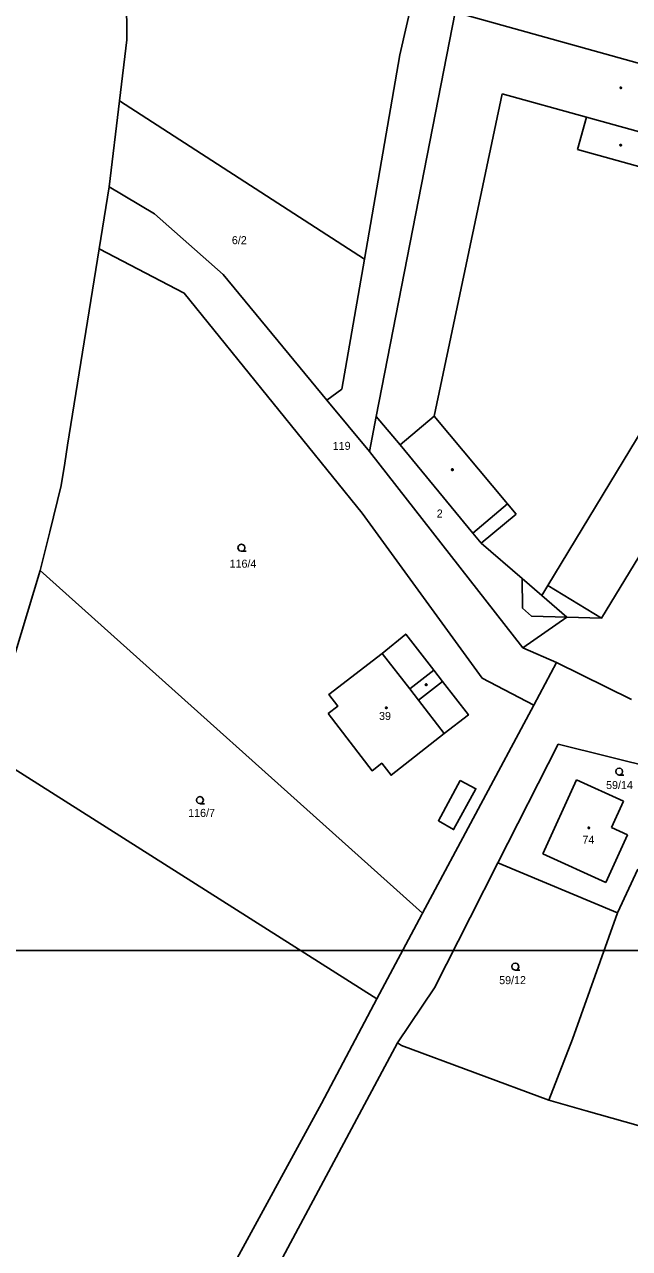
# Model space of a CAD drawing. Extents: x -752500 to -750336, y -1035826 to -1033500.
# Drawn here: x -751692 to -751563.4, y -1034563.3 to -1034303.4 of the extents above; entities that cross this region are included whole.
import ezdxf

# ---------------------------------------------------------------- set-up
doc = ezdxf.new("R2010")
doc.units = 0
for name, color, linetype in [('Default', 7, 'Continuous'), ('Hranice parcel', 7, 'Continuous'), ('ML1000', 7, 'Continuous'), ('Parcelní čísla', 7, 'Continuous'), ('Vnitřní kresba', 7, 'Continuous'), ('Věcná břemena k části', 7, 'Continuous'), ('Značky budov', 7, 'Continuous'), ('Značky kultur', 7, 'Continuous')]:
    doc.layers.add(name, color=color, linetype=linetype)

# ---------------------------------------------------------------- blocks, each defined once
blk = doc.blocks.new('304')
at = {"layer": 'Default'}
blk.add_lwpolyline([(0, 0), (-0.38, 0.1), (-0.65, 0.37), (-0.75, 0.74), (-0.65, 1.11), (-0.38, 1.38), (-0.01, 1.48), (0.36, 1.38), (0.63, 1.11), (0.73, 0.73), (0.63, 0.35), (0.36, 0.08), (-0.02, -0.02), (0.98, -0.02)], dxfattribs=at)
blk = doc.blocks.new('402')
at = {"layer": 'Default'}
blk.add_lwpolyline([(0.09, 0.15), (0.18, 0), (0.09, -0.15), (-0.09, -0.15), (-0.18, 0), (-0.09, 0.15), (0.09, 0.15)], dxfattribs=at)

msp = doc.modelspace()

# ---------------------------------------------------------------- linework, layer by layer
at = {"layer": 'Hranice parcel'}
for p, q in [((-751670.81, -1034226.35), (-751670.25, -1034306.59)), ((-751612.23, -1034309.8), (-751603.35, -1034270.82)), ((-751600.51, -1034300.74), (-751617.27, -1034386.59)), ((-751671.8, -1034319.6), (-751670.25, -1034306.59)), ((-751619.79, -1034353.2), (-751612.23, -1034309.8)), ((-751673.98, -1034337.87), (-751671.8, -1034319.6)), ((-751671.8, -1034319.6), (-751619.79, -1034353.2)), ((-751676.11, -1034351.03), (-751673.98, -1034337.87)), ((-751673.98, -1034337.87), (-751664.36, -1034343.6)), ((-751664.36, -1034343.6), (-751649.76, -1034356.45)), ((-751682.84, -1034392.69), (-751676.11, -1034351.03)), ((-751676.11, -1034351.03), (-751658.05, -1034360.39)), ((-751624.6, -1034380.78), (-751619.79, -1034353.2)), ((-751649.76, -1034356.45), (-751627.74, -1034383.13)), ((-751658.05, -1034360.39), (-751620.28, -1034407.14)), ((-751624.6, -1034380.78), (-751627.74, -1034383.13)), ((-751627.74, -1034383.13), (-751618.73, -1034394.05)), ((-751617.27, -1034386.59), (-751618.73, -1034394.05)), ((-751612.21, -1034392.61), (-751617.27, -1034386.59)), ((-751683.46, -1034396.55), (-751682.84, -1034392.69)), ((-751596.76, -1034411.38), (-751612.21, -1034392.61)), ((-751618.73, -1034394.05), (-751586.12, -1034435.76)), ((-751684.22, -1034401.25), (-751683.46, -1034396.55)), ((-751686.63, -1034411.12), (-751684.22, -1034401.25)), ((-751620.28, -1034407.14), (-751594.74, -1034442.18)), ((-751569.4, -1034429.41), (-751556.65, -1034408.47)), ((-751688.64, -1034419.35), (-751686.63, -1034411.12)), ((-751594.98, -1034413.54), (-751596.76, -1034411.38)), ((-751586.29, -1034421.03), (-751594.98, -1034413.54)), ((-751700.27, -1034457.61), (-751688.64, -1034419.35)), ((-751688.64, -1034419.35), (-751607.43, -1034492.1)), ((-751582.1, -1034424.64), (-751586.29, -1034421.03)), ((-751576.79, -1034429.21), (-751582.1, -1034424.64)), ((-751576.79, -1034429.21), (-751586.12, -1034435.76)), ((-751569.4, -1034429.41), (-751576.79, -1034429.21)), ((-751615.98, -1034436.92), (-751610.98, -1034432.81)), ((-751610.98, -1034432.81), (-751605.03, -1034440.5)), ((-751627.37, -1034445.67), (-751615.98, -1034436.92)), ((-751578.94, -1034438.89), (-751586.12, -1034435.76)), ((-751605.03, -1034440.5), (-751603.2, -1034442.87)), ((-751578.94, -1034438.89), (-751583.78, -1034447.94)), ((-751563, -1034446.73), (-751578.94, -1034438.89)), ((-751603.2, -1034442.87), (-751597.68, -1034450)), ((-751594.74, -1034442.18), (-751583.78, -1034447.94)), ((-751627.37, -1034445.67), (-751625.46, -1034448.16)), ((-751625.46, -1034448.16), (-751627.48, -1034449.72)), ((-751583.78, -1034447.94), (-751607.43, -1034492.1)), ((-751627.48, -1034449.72), (-751618.16, -1034461.83)), ((-751597.68, -1034450), (-751602.8, -1034453.9)), ((-751614.11, -1034462.79), (-751602.8, -1034453.9)), ((-751578.63, -1034456.23), (-751591.42, -1034481.41)), ((-751557.12, -1034461.54), (-751578.63, -1034456.23)), ((-751617.15, -1034510.28), (-751700.27, -1034457.61)), ((-751618.16, -1034461.83), (-751616.1, -1034460.25)), ((-751616.1, -1034460.25), (-751614.11, -1034462.79)), ((-751574.75, -1034463.78), (-751581.87, -1034479.49)), ((-751564.73, -1034468.32), (-751574.75, -1034463.78)), ((-751567.27, -1034473.92), (-751564.73, -1034468.32)), ((-751563.9, -1034475.45), (-751567.27, -1034473.92)), ((-751568.48, -1034485.56), (-751563.9, -1034475.45)), ((-751581.87, -1034479.49), (-751568.48, -1034485.56)), ((-751591.42, -1034481.41), (-751597.29, -1034492.98)), ((-751591.42, -1034481.41), (-751566, -1034492.05)), ((-751566, -1034492.05), (-751561.66, -1034482.75)), ((-751607.57, -1034492.37), (-751617.15, -1034510.28)), ((-751607.43, -1034492.1), (-751607.57, -1034492.37)), ((-751575.6, -1034518.88), (-751566, -1034492.05)), ((-751597.29, -1034492.98), (-751604.89, -1034507.95)), ((-751612.74, -1034519.66), (-751604.89, -1034507.95)), ((-751617.15, -1034510.28), (-751628.92, -1034532.53)), ((-751612.74, -1034519.66), (-751642.72, -1034575.65)), ((-751611.9, -1034520.17), (-751612.74, -1034519.66)), ((-751580.59, -1034531.81), (-751611.9, -1034520.17)), ((-751580.59, -1034531.81), (-751575.6, -1034518.88)), ((-751628.92, -1034532.53), (-751651.03, -1034573.04)), ((-751580.59, -1034531.81), (-751572.63, -1034534.09)), ((-751572.63, -1034534.09), (-751558.88, -1034537.93))]:
    msp.add_line(p, q, dxfattribs=at)
at = {"layer": 'ML1000'}
msp.add_lwpolyline([(-751250, -1034500), (-751875, -1034500), (-752500, -1034500)], dxfattribs=at)
at = {"layer": 'Vnitřní kresba'}
for p, q in [((-751600.51, -1034300.74), (-751527.21, -1034321.17)), ((-751604.96, -1034386.54), (-751590.54, -1034318.07)), ((-751572.59, -1034323.07), (-751590.54, -1034318.07)), ((-751520.57, -1034323.02), (-751580.81, -1034422.5)), ((-751574.51, -1034329.93), (-751572.59, -1034323.07)), ((-751555.76, -1034327.75), (-751572.59, -1034323.07)), ((-751557.68, -1034334.62), (-751574.51, -1034329.93)), ((-751604.96, -1034386.54), (-751612.21, -1034392.61)), ((-751604.96, -1034386.54), (-751589.36, -1034405.19)), ((-751596.76, -1034411.38), (-751589.36, -1034405.19)), ((-751589.36, -1034405.19), (-751587.56, -1034407.34)), ((-751587.56, -1034407.34), (-751594.98, -1034413.54)), ((-751586.22, -1034427.34), (-751586.29, -1034421.03)), ((-751580.81, -1034422.5), (-751582.1, -1034424.64)), ((-751580.81, -1034422.5), (-751569.4, -1034429.41)), ((-751584.28, -1034429.01), (-751586.22, -1034427.34)), ((-751576.79, -1034429.21), (-751584.28, -1034429.01)), ((-751610.13, -1034444.45), (-751615.98, -1034436.92)), ((-751610.13, -1034444.45), (-751605.03, -1034440.5)), ((-751608.29, -1034446.82), (-751603.2, -1034442.87)), ((-751608.29, -1034446.82), (-751610.13, -1034444.45)), ((-751602.8, -1034453.9), (-751608.29, -1034446.82))]:
    msp.add_line(p, q, dxfattribs=at)
at = {"layer": 'Věcná břemena k části'}
for points in [[(-751688.64, -1034419.35), (-751686.63, -1034411.12), (-751684.22, -1034401.25), (-751683.46, -1034396.55), (-751682.84, -1034392.69), (-751676.11, -1034351.03), (-751658.05, -1034360.39), (-751620.28, -1034407.14), (-751594.74, -1034442.18), (-751583.78, -1034447.94), (-751607.43, -1034492.1)], [(-751627.48, -1034449.72), (-751618.16, -1034461.83), (-751616.1, -1034460.25), (-751614.11, -1034462.79), (-751602.8, -1034453.9), (-751597.68, -1034450), (-751603.2, -1034442.87), (-751605.03, -1034440.5), (-751610.98, -1034432.81), (-751615.98, -1034436.92), (-751627.37, -1034445.67), (-751625.46, -1034448.16)], [(-751599.41, -1034463.9), (-751604.07, -1034472.47), (-751600.84, -1034474.34), (-751596.1, -1034465.66)]]:
    msp.add_lwpolyline(points, close=True, dxfattribs=at)

# ---------------------------------------------------------------- block references
at = {"layer": 'Značky budov'}
for p in [(-751565.31, -1034316.8), (-751565.33, -1034328.97), (-751601.08, -1034397.9), (-751606.66, -1034443.56), (-751615.12, -1034448.48), (-751572.11, -1034473.96)]:
    msp.add_blockref('402', p, dxfattribs=at)
at = {"layer": 'Značky kultur'}
for p in [(-751645.91, -1034415.22), (-751565.64, -1034462.75), (-751654.71, -1034468.82), (-751587.71, -1034504.18)]:
    msp.add_blockref('304', p, dxfattribs=at)

# ---------------------------------------------------------------- texts
at = {"layer": 'Parcelní čísla'}
for s, p in [('6/2', (-751647.94, -1034350.02)), ('119', (-751626.51, -1034393.7)), ('2', (-751604.41, -1034408.07)), ('116/4', (-751648.42, -1034418.72)), ('39', (-751616.67, -1034451.06)), ('59/14', (-751568.43, -1034465.73)), ('116/7', (-751657.22, -1034471.65)), ('74', (-751573.45, -1034477.33)), ('59/12', (-751591.15, -1034507.16))]:
    msp.add_text(s, height=1.7, dxfattribs=at).set_placement(p)

doc.saveas('drawing.dxf')
